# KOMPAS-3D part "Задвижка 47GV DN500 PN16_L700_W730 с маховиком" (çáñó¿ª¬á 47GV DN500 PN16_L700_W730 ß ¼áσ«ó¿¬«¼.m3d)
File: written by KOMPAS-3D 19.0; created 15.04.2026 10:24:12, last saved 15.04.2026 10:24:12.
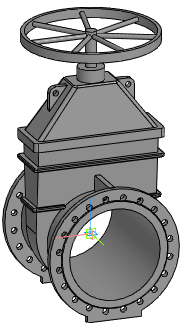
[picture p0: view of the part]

Document properties: Автор: Евгений; Полное имя файла: Z:\3.Личные\kachalov\3d для проектировщиков\2.1 Тип 47GV, 47GV.Z\Задвижка 47GV_DN40-DN600\stp_Задвижка 47GV\Задвижка 47GV DN500 PN16_L700_W730 с маховиком.m3d

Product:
- Part/product: Задвижка 47GV DN500 PN16_L700_W730 с маховиком

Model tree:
1. Операция без истории:1  (labels: Задвижка 47GV DN500 PN16_L700_W730 с маховиком)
